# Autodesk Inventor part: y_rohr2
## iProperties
Created: 2005-04
Part Number: y_rohr2
Cost Center: 0 kg
Material: 1.0037 St 37-2
Document SubType Name: Modeling
Designer: juergen
Authority: 0 mm^3
Manufacturer: Standard
Standards Organization: Custom
Author: juergen
SaveDate: 2004-12-09
SaveTime: 10:15
TotalMass: 0 kg
TotalVolume: 0 mm^3
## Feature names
1. Sweeping1
2. Runde Anordnung1 [Circular Pattern]
3. Wandstärke1
